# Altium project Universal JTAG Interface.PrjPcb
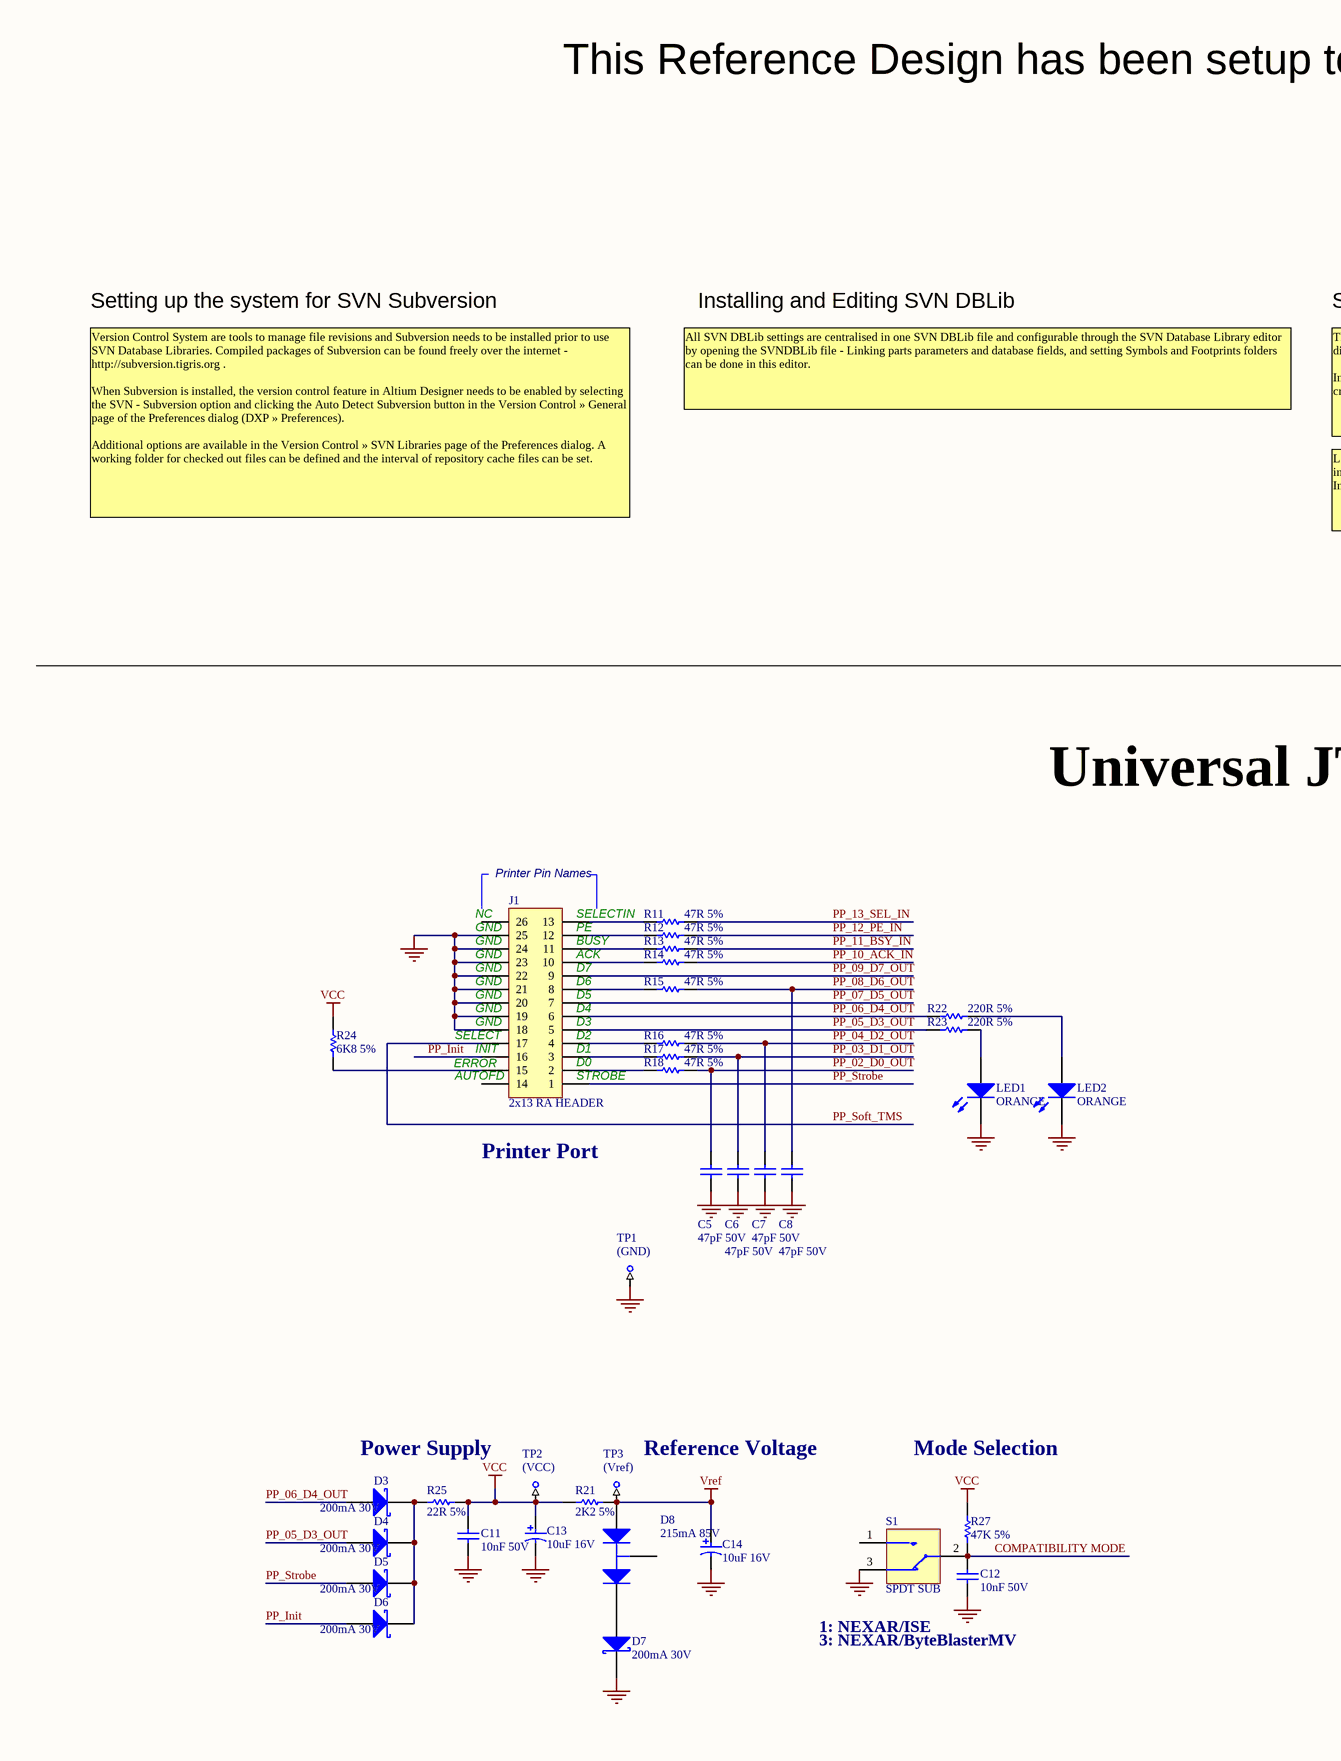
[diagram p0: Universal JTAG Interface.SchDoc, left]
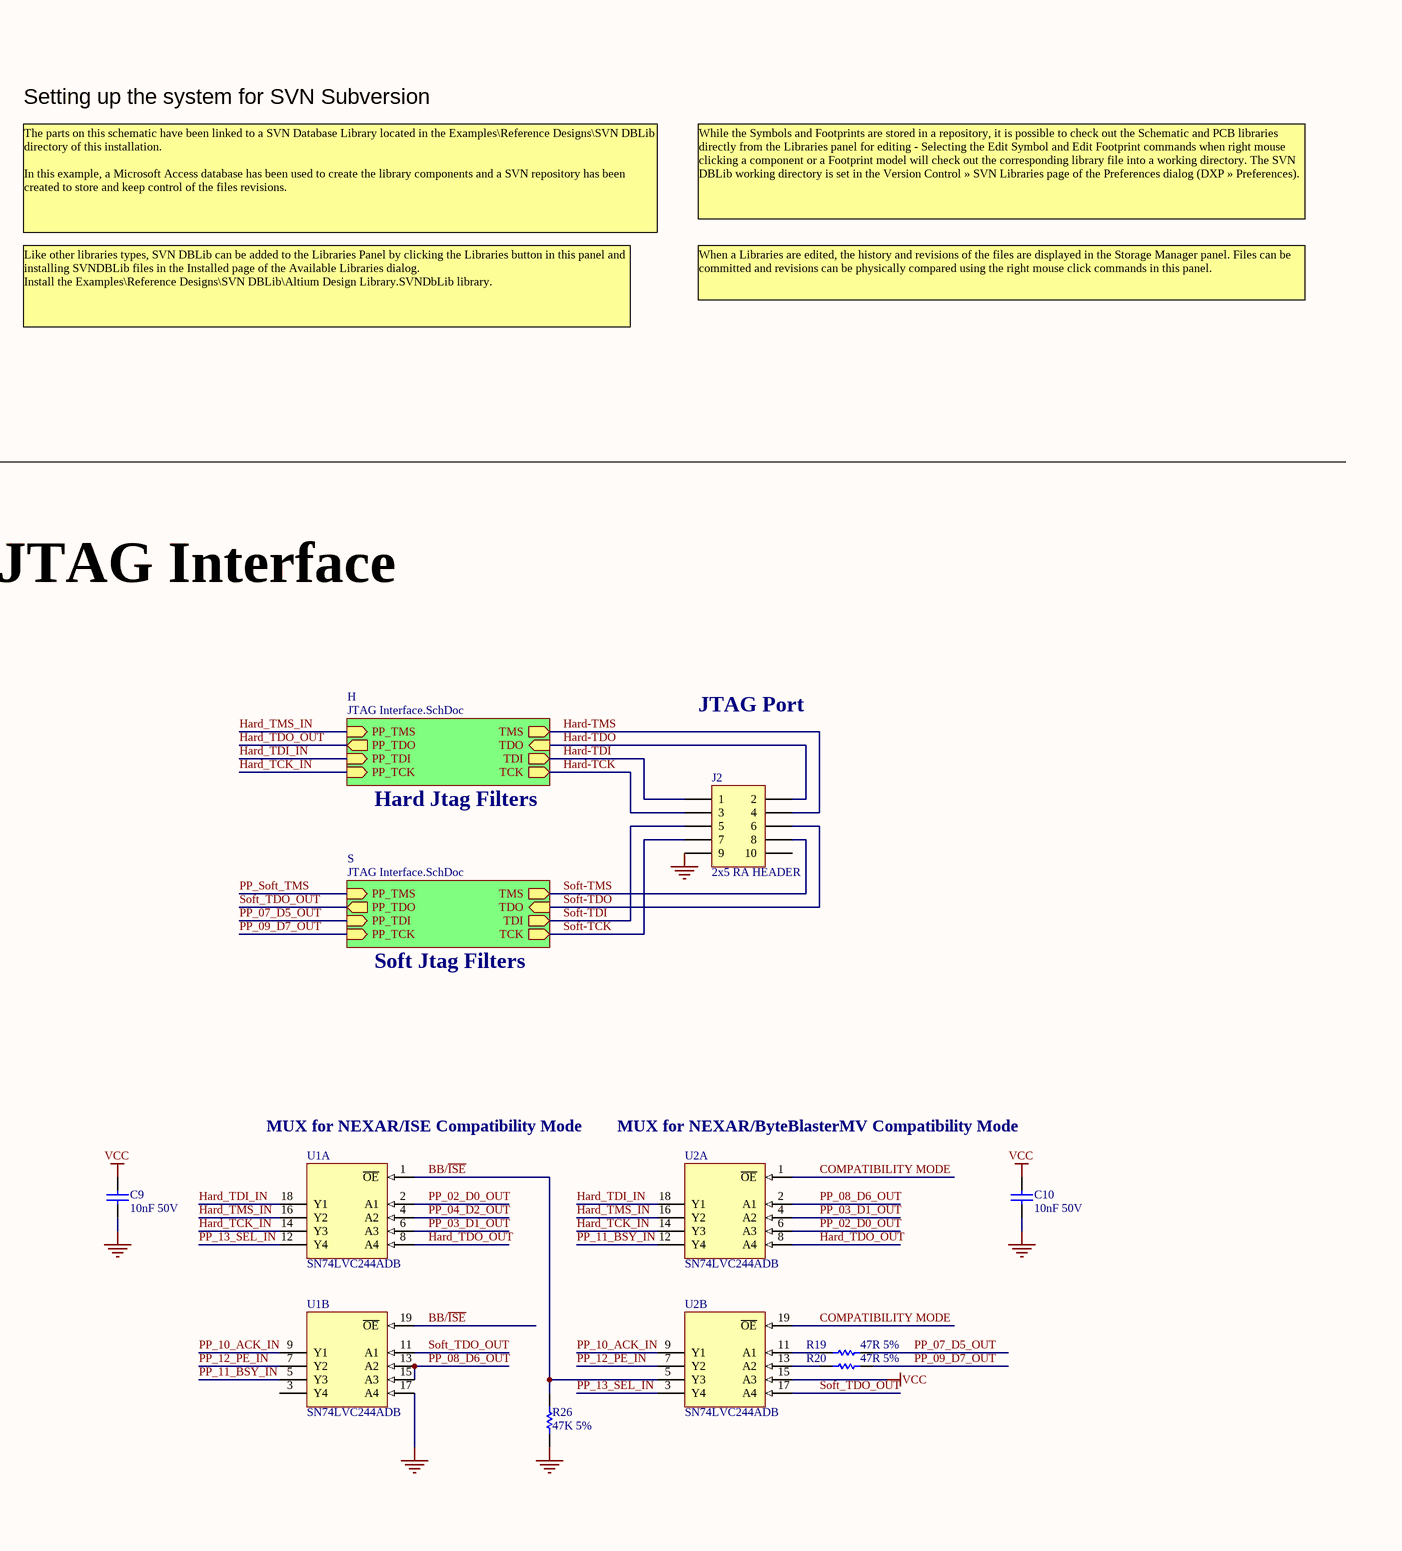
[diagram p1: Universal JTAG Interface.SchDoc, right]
2 sheets, 79 parts. Net scope: hierarchical (ports join the sheet entries above them; power ports are global).
Board file: Universal JTAG Interface.PcbDoc
Sheets:
  Universal JTAG Interface.SchDoc
    H = JTAG Interface.SchDoc
    S = JTAG Interface.SchDoc

## Sheet Universal JTAG Interface.SchDoc: Universal JTAG Interface Rev 1.11
size C; Organization: Altium Limited; Address1: L3, 12a Rodborough Rd; Address2: Frenchs Forest; Address3: NSW; Address4: Australia 2086; DocumentNumber: 1; Revision: 1.11; SheetNumber: 1; SheetTotal: 2

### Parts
C5  47pF 50V  [CAPC2012]
C6  47pF 50V  [CAPC2012]
C7  47pF 50V  [CAPC2012]
C8  47pF 50V  [CAPC2012]
C9  10nF 50V  [CAPC2012]
C10  10nF 50V  [CAPC2012]
C11  10nF 50V  [CAPC2012]
C12  10nF 50V  [CAPC2012]
C13  10uF 16V  [CAPC3528]
C14  10uF 16V  [CAPC3528]
D3  200mA 30V  [SOT95P230-3]
D4  200mA 30V  [SOT95P230-3]
D5  200mA 30V  [SOT95P230-3]
D6  200mA 30V  [SOT95P230-3]
D7  200mA 30V  [SOT95P230-3]
D8  215mA 85V  [SOT95P230-3]
J1  2x13 RA HEADER  [HDR2X13_RA_CENTRONICS]
J2  2x5 RA HEADER  [918510x323]
LED1  ORANGE  [LED3528]
LED2  ORANGE  [LED3528]
R11  47R 5%  [RESC2012]
R12  47R 5%  [RESC2012]
R13  47R 5%  [RESC2012]
R14  47R 5%  [RESC2012]
R15  47R 5%  [RESC2012]
R16  47R 5%  [RESC2012]
R17  47R 5%  [RESC2012]
R18  47R 5%  [RESC2012]
R19  47R 5%  [RESC2012]
R20  47R 5%  [RESC2012]
R21  2K2 5%  [RESC2012]
R22  220R 5%  [RESC2012]
R23  220R 5%  [RESC2012]
R24  6K8 5%  [RESC2012]
R25  22R 5%  [RESC2012]
R26  47K 5%  [RESC2012]
R27  47K 5%  [RESC2012]
S1  SPDT SUB  [OS102011MA1QN1]
TP1  (GND)  [TestPin]  (no BOM)
TP2  (VCC)  [TestPin]  (no BOM)
TP3  (Vref)  [TestPin]  (no BOM)
U1  SN74LVC244ADB  [SOP65P780-20]  (parts A,B of 2)
U2  SN74LVC244ADB  [SOP65P780-20]  (parts A,B of 2)

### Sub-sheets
H = JTAG Interface.SchDoc: TDO (in), TDI (out), TCK (out), TMS (out), PP_TDO (out), PP_TDI (in), PP_TCK (in), PP_TMS (in)
S = JTAG Interface.SchDoc: TDO (in), TDI (out), TCK (out), TMS (out), PP_TDO (out), PP_TDI (in), PP_TCK (in), PP_TMS (in)

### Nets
GND: C5.2 C6.2 C7.2 C8.2 C9.1 C10.1 C11.1 C12.1 C13.2 C14.2 D7.3(k) J1.18 J1.19 J1.20 J1.21 J1.22 J1.23 J1.24 J1.25 J2.9 LED1.2(K) LED2.2(K) R26.2 S1.3 S1.M1 S1.M2 TP1.1 U1.10(GND) U1.17(A4) U2.10(GND)
VCC: C9.2 C10.2 C11.2 C13.1 R21.2 R24.1 R25.1 R27.1 TP2.1 U1.20(VCC) U2.15(A3) U2.20(VCC)
Vref: C14.1 D8.1(A) R21.1 TP3.1
BB/~{ISE}: R26.1 U1.1(~{OE}) U1.19(~{OE}) U2.5(Y3)
COMPATIBILITY MODE: C12.2 R27.2 S1.2 U2.1(~{OE}) U2.19(~{OE})
Hard-TCK: J2.3 ; sheet H/TCK
Hard-TDI: J2.1 ; sheet H/TDI
Hard-TDO: J2.2 ; sheet H/TDO
Hard-TMS: J2.4 ; sheet H/TMS
Hard_TCK_IN: U1.14(Y3) U2.14(Y3) ; sheet H/PP_TCK
Hard_TDI_IN: U1.18(Y1) U2.18(Y1) ; sheet H/PP_TDI
Hard_TDO_OUT: U1.8(A4) U2.8(A4) ; sheet H/PP_TDO
Hard_TMS_IN: U1.16(Y2) U2.16(Y2) ; sheet H/PP_TMS
PP_02_D0_OUT: C5.1 R18.1 U1.2(A1) U2.6(A3)
PP_03_D1_OUT: C6.1 R17.1 U1.6(A3) U2.4(A2)
PP_04_D2_OUT: C7.1 R16.1 U1.4(A2)
PP_05_D3_OUT: D4.1(A) J1.5 R23.2
PP_06_D4_OUT: D3.1(A) J1.6 R22.2
PP_07_D5_OUT: J1.7 R19.1 ; sheet S/PP_TDI
PP_08_D6_OUT: C8.1 R15.1 U1.13(A2) U1.15(A3) U2.2(A1)
PP_09_D7_OUT: J1.9 R20.1 ; sheet S/PP_TCK
PP_10_ACK_IN: R14.1 U1.9(Y1) U2.9(Y1)
PP_11_BSY_IN: R13.1 U1.5(Y3) U2.12(Y4)
PP_12_PE_IN: R12.1 U1.7(Y2) U2.7(Y2)
PP_13_SEL_IN: R11.1 U1.12(Y4) U2.3(Y4)
PP_Init: D6.1(A) J1.16
PP_Soft_TMS: J1.17 ; sheet S/PP_TMS
PP_Strobe: D5.1(A) J1.1
Soft-TCK: J2.7 ; sheet S/TCK
Soft-TDI: J2.5 ; sheet S/TDI
Soft-TDO: J2.6 ; sheet S/TDO
Soft-TMS: J2.8 ; sheet S/TMS
Soft_TDO_OUT: U1.11(A1) U2.17(A4) ; sheet S/PP_TDO
NetD3_3: D3.3(k) D4.3(k) D5.3(k) D6.3(k) R25.2
NetD7_1: D7.1(A) D8.2(K)
NetJ1_2: J1.2 R18.2
NetJ1_3: J1.3 R17.2
NetJ1_4: J1.4 R16.2
NetJ1_8: J1.8 R15.2
NetJ1_10: J1.10 R14.2
NetJ1_11: J1.11 R13.2
NetJ1_12: J1.12 R12.2
NetJ1_13: J1.13 R11.2
NetJ1_15: J1.15 R24.2
NetLED1_1: LED1.1(A) R23.1
NetLED2_1: LED2.1(A) R22.1
NetR19_2: R19.2 U2.11(A1)
NetR20_2: R20.2 U2.13(A2)

Not connected (* = marked no-connect by the designer): D3 2; D4 2; D5 2; D6 2; D7 2; D8 3(C); J1 14 26; J2 10; S1 1; U1 3(Y4)

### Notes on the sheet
- This Reference Design has been setup to illustrate the use of SVN DBLib in Altium Designer.
- Setting up the system for SVN Subversion
- Installing and Editing SVN DBLib
- All SVN DBLib settings are centralised in one SVN DBLib file and configurable through the SVN Database Library editor by opening the SVNDBLib file - Linking parts parameters and database fields, and setting Symbols and Footprints folders can be done in this editor.
- The parts on this schematic have been linked to a SVN Database Library located in the Examples\Reference Designs\SVN DBLib directory of this installation.
  In this example, a Microsoft Access database has been used to create the library components and a SVN repository has been created to store and keep control of the files revisions.
- While the Symbols and Footprints are stored in a repository, it is possible to check out the Schematic and PCB libraries directly from the Libraries panel for editing - Selecting the Edit Symbol and Edit Footprint commands when right mouse clicking a component or a Footprint model will check out the corresponding library file into a working directory. The SVN DBLib working directory is set in the Version Control » SVN Libraries page of the Preferences dialog (DXP » Preferences).
- When a Libraries are edited, the history and revisions of the files are displayed in the Storage Manager panel. Files can be committed and revisions can be physically compared using the right mouse click commands in this panel.
- Version Control System are tools to manage file revisions and Subversion needs to be installed prior to use SVN Database Libraries. Compiled packages of Subversion can be found freely over the internet - http://subversion.tigris.org .
  When Subversion is installed, the version control feature in Altium Designer needs to be enabled by selecting the SVN - Subversion option and clicking the Auto Detect Subversion button in the Version Control » General page of the Preferences dialog (DXP » Preferences).
  Additional options are available in the Version Control » SVN Libraries page of the Preferences dialog. A working folder for checked out files can be defined and the interval of repository cache files can be set.
- Like other libraries types, SVN DBLib can be added to the Libraries Panel by clicking the Libraries button in this panel and installing SVNDBLib files in the Installed page of the Available Libraries dialog.
  Install the Examples\Reference Designs\SVN DBLib\Altium Design Library.SVNDbLib library.
- Universal JTAG Interface
- (near J1) Printer Pin Names
- (near J1) GND
- (near J1) NC
- (near J1) SELECTIN
- (near J1) PE
- (near J1) BUSY
- (near J1) ACK
- (near J1) D7
- JTAG Port
- (near J1) SELECT
- (near J1) D2
- (near J1) D3
- (near J1) D4
- (near J1) D5
- (near J1) D6
- Hard Jtag Filters
- (near J1) ERROR
- (near J1) AUTOFD
- (near J1) INIT
- (near J1) STROBE
- (near J1) D0
- (near J1) D1
- Printer Port
- Soft Jtag Filters
- (near U1) MUX for NEXAR/ISE Compatibility Mode
- MUX for NEXAR/ByteBlasterMV Compatibility Mode
- Power Supply
- Reference Voltage
- Mode Selection
- 1: NEXAR/ISE
- 3: NEXAR/ByteBlasterMV

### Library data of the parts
C5-C12 = CAP-NP: Capacitor
C13 C14 = CAP-P: Polar Capacitor
D3-D7 = DIO-SCHOTTKY-1S-SOT23: Schottky Barrier Single Diode
D8 = DIO-2S: Silicon Switching Diode Array for High-Speed Switching
J1 = CON-IDC-2x13-M-RA: Header, 13-Pin, Dual row
J2 = CON-IDC-2x5-M-RA: Header, 5-Pin, Dual row, Right angle boxed
LED1 LED2 = DIO-LED-1S: Typical GREEN SMD LED Agilent make
R11-R27 = RES: Resistor
S1 = SWI-TOG-SPDT-OS102011MA1QN1: SPDT Subminiature Toggle Switch
TP1-TP3 = TestPin
U1 U2 = SN74LVC244: Octal Buffer/Driver with 3-State Outputs

## Sheet JTAG Interface.SchDoc: Universal JTAG Interface Rev 1.11
size A; Organization: Altium Limited; Address1: L3, 12a Rodborough Rd; Address2: Frenchs Forest; Address3: NSW; Address4: Australia 2086; DocumentNumber: 2; SheetNumber: 2; SheetTotal: 2
Used 2 times, as channels H, S. Parts and nets are listed once, with the designators drawn on the sheet.
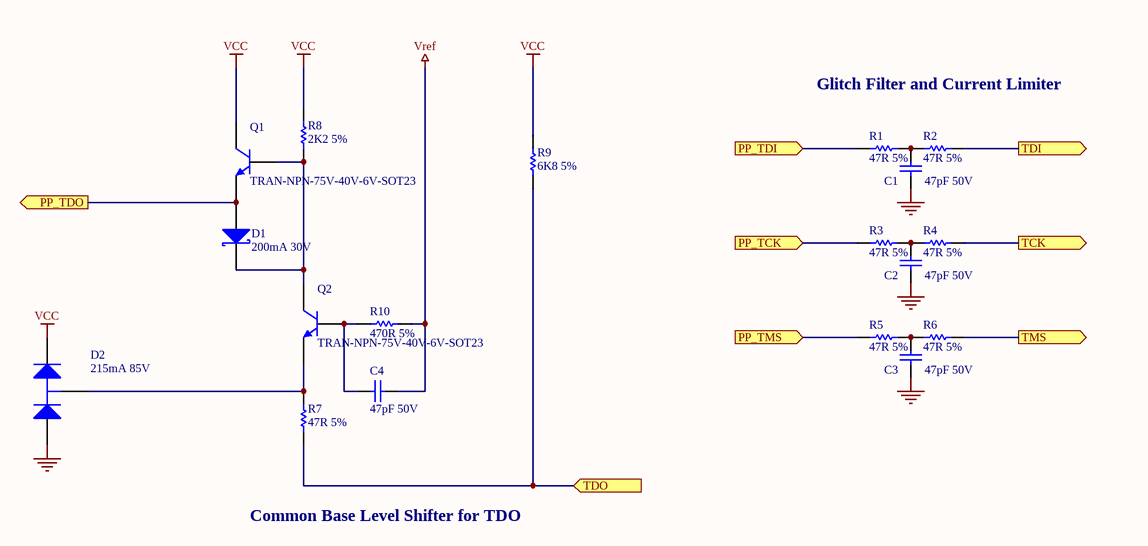
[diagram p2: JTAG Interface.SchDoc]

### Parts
C1  47pF 50V  [CAPC2012]
C2  47pF 50V  [CAPC2012]
C3  47pF 50V  [CAPC2012]
C4  47pF 50V  [CAPC2012]
D1  200mA 30V  [SOT95P230-3]
D2  215mA 85V  [SOT95P230-3]
Q1  TRAN-NPN-75V-40V-6V-SOT23  [SOT95P230-3]
Q2  TRAN-NPN-75V-40V-6V-SOT23  [SOT95P230-3]
R1  47R 5%  [RESC2012]
R2  47R 5%  [RESC2012]
R3  47R 5%  [RESC2012]
R4  47R 5%  [RESC2012]
R5  47R 5%  [RESC2012]
R6  47R 5%  [RESC2012]
R7  47R 5%  [RESC2012]
R8  2K2 5%  [RESC2012]
R9  6K8 5%  [RESC2012]
R10  470R 5%  [RESC2012]

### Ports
PP_TCK (in), PP_TDI (in), PP_TDO (out), PP_TMS (in), TCK (out), TDI (out), TDO (in), TMS (out)

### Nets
GND: C1.2 C2.2 C3.2 D2.1(A)
VCC: D2.2(K) Q1.3(C) R8.2 R9.2
Vref: C4.2 R10.1
PP_TCK: R3.1 ; port PP_TCK
PP_TDI: R1.1 ; port PP_TDI
PP_TDO: D1.1(A) Q1.2(E) ; port PP_TDO
PP_TMS: R5.1 ; port PP_TMS
TCK: R4.2 ; port TCK
TDI: R2.2 ; port TDI
TDO: R7.1 R9.1 ; port TDO
TMS: R6.2 ; port TMS
NetC1_1: C1.1 R1.2 R2.1
NetC2_1: C2.1 R3.2 R4.1
NetC3_1: C3.1 R5.2 R6.1
NetC4_1: C4.1 Q2.1(B) R10.2
NetD1_3: D1.3(k) Q1.1(B) Q2.3(C) R8.1
NetD2_3: D2.3(C) Q2.2(E) R7.2

Not connected (* = marked no-connect by the designer): D1 2

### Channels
H: designators end in H; ports PP_TCK=Hard_TCK_IN PP_TDI=Hard_TDI_IN PP_TDO=Hard_TDO_OUT PP_TMS=Hard_TMS_IN TCK=Hard-TCK TDI=Hard-TDI TDO=Hard-TDO TMS=Hard-TMS
S: designators end in S; ports PP_TCK=PP_09_D7_OUT PP_TDI=PP_07_D5_OUT PP_TDO=Soft_TDO_OUT PP_TMS=PP_Soft_TMS TCK=Soft-TCK TDI=Soft-TDI TDO=Soft-TDO TMS=Soft-TMS

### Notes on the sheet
- Glitch Filter and Current Limiter
- Common Base Level Shifter for TDO

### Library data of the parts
C1-C4 = CAP-NP: Capacitor
D1 = DIO-SCHOTTKY-1S-SOT23: Schottky Barrier Single Diode
D2 = DIO-2S: as D8 on sheet Universal JTAG Interface
Q1 Q2 = TRA-NPN: General Purpose Transistor NPN Silicon
R1-R10 = RES: Resistor

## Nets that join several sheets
GND: Universal JTAG Interface (30 pins), H (C1H.2 C2H.2 C3H.2 D2H.1), S (C1S.2 C2S.2 C3S.2 D2S.1)
VCC: Universal JTAG Interface (12 pins), H (D2H.2 Q1H.3 R8H.2 R9H.2), S (D2S.2 Q1S.3 R8S.2 R9S.2)
Vref: Universal JTAG Interface (C14.1 D8.1 R21.1 TP3.1), H (C4H.2 R10H.1), S (C4S.2 R10S.1)
Hard-TCK: Universal JTAG Interface (J2.3), H (R4H.2)
Hard-TDI: Universal JTAG Interface (J2.1), H (R2H.2)
Hard-TDO: Universal JTAG Interface (J2.2), H (R7H.1 R9H.1)
Hard-TMS: Universal JTAG Interface (J2.4), H (R6H.2)
Hard_TCK_IN: Universal JTAG Interface (U1.14 U2.14), H (R3H.1)
Hard_TDI_IN: Universal JTAG Interface (U1.18 U2.18), H (R1H.1)
Hard_TDO_OUT: Universal JTAG Interface (U1.8 U2.8), H (D1H.1 Q1H.2)
Hard_TMS_IN: Universal JTAG Interface (U1.16 U2.16), H (R5H.1)
PP_07_D5_OUT: Universal JTAG Interface (J1.7 R19.1), S (R1S.1)
PP_09_D7_OUT: Universal JTAG Interface (J1.9 R20.1), S (R3S.1)
PP_Soft_TMS: Universal JTAG Interface (J1.17), S (R5S.1)
Soft-TCK: Universal JTAG Interface (J2.7), S (R4S.2)
Soft-TDI: Universal JTAG Interface (J2.5), S (R2S.2)
Soft-TDO: Universal JTAG Interface (J2.6), S (R7S.1 R9S.1)
Soft-TMS: Universal JTAG Interface (J2.8), S (R6S.2)
Soft_TDO_OUT: Universal JTAG Interface (U1.11 U2.17), S (D1S.1 Q1S.2)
